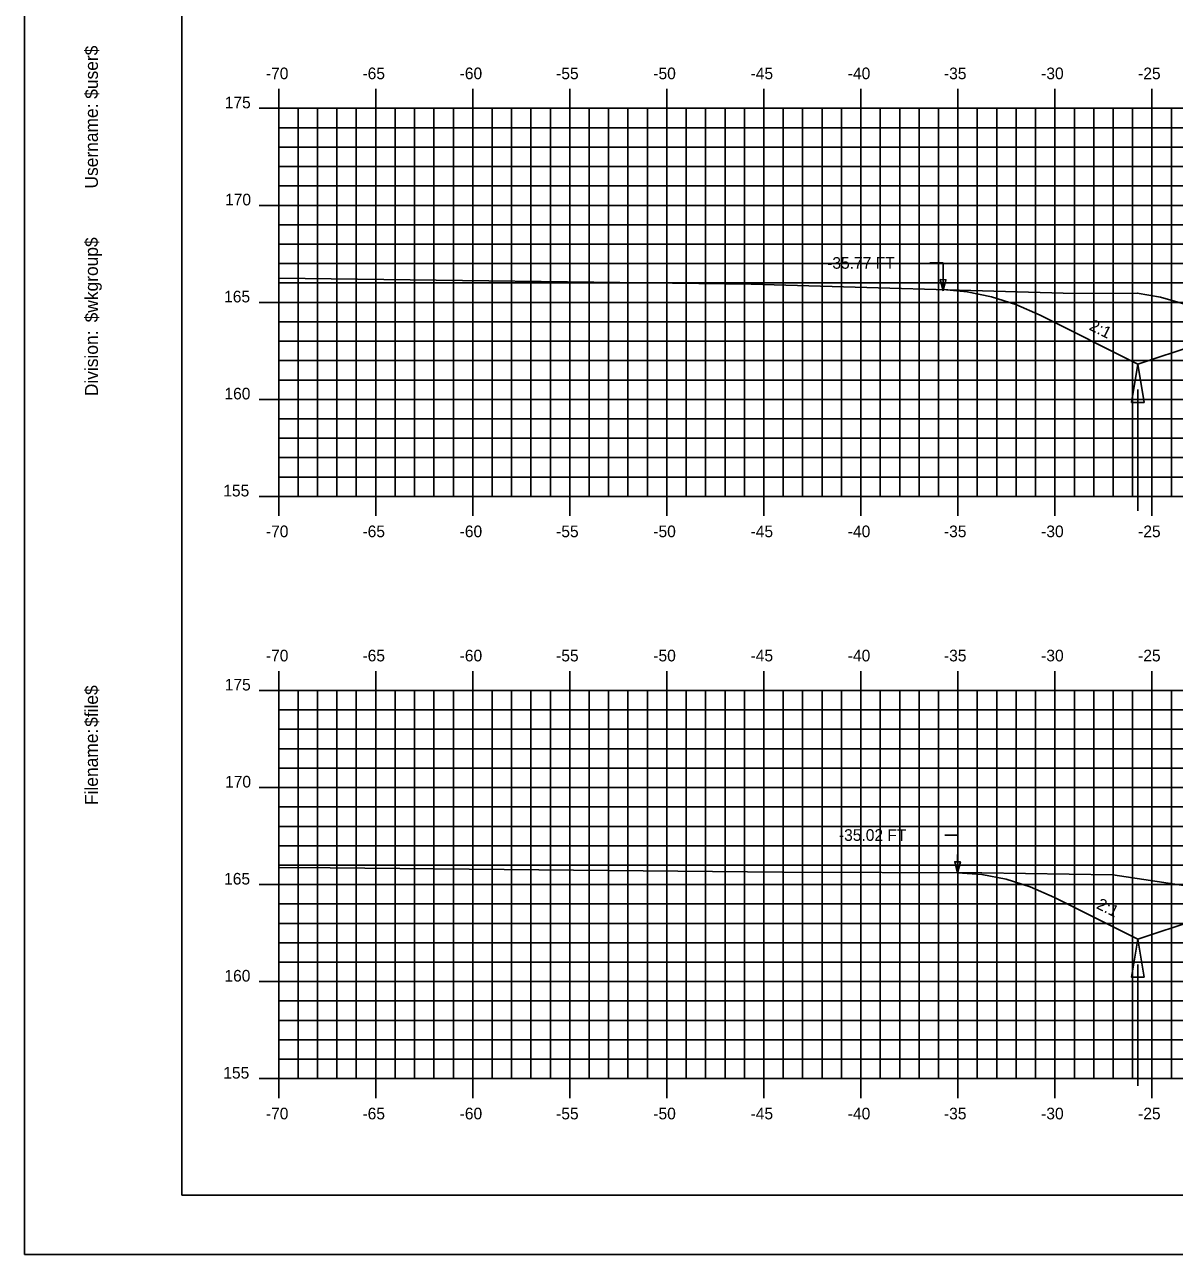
# Model space of a CAD drawing. Extents: x 1142533 to 1142703, y 608981 to 609091.
# Drawn here: x 1142533 to 1142592.2, y 608981.3 to 609044.6 of the extents above; entities that cross this region are included whole.
import ezdxf

# ---------------------------------------------------------------- set-up
doc = ezdxf.new("R2010")
doc.units = 0
for name, color, linetype in [('ANNOTATION', 7, 'Continuous'), ('BORDER', 7, 'Continuous'), ('D_Drainage_Ditch_Line', 7, 'Continuous'), ('D_Roadway_SlopeLines', 7, 'Continuous'), ('D_Text_Standard', 7, 'Continuous'), ('H_V ANNOTATION', 7, 'Continuous'), ('MAJOR', 7, 'Continuous'), ('MINOR', 7, 'Continuous'), ('PLOT BOUNDARY', 7, 'Continuous'), ('S_Roadway_Centerline', 7, 'Continuous')]:
    doc.layers.add(name, color=color, linetype=linetype)

msp = doc.modelspace()

# ---------------------------------------------------------------- linework, layer by layer
for points in [[(1142580.286, 609030.994), (1142581.536, 609030.885), (1142582.786, 609030.628), (1142584.036, 609030.224), (1142585.286, 609029.673), (1142590.329, 609027.152), (1142593.329, 609028.152), (1142601.052, 609030.726), (1142601.053, 609030.726), (1142605.053, 609030.886), (1142616.053, 609031.106), (1142627.053, 609030.886), (1142631.053, 609030.726), (1142638.777, 609028.152), (1142641.777, 609027.152), (1142645.788, 609029.157), (1142647.038, 609029.701), (1142648.288, 609030.083), (1142649.538, 609030.303), (1142650.788, 609030.361)], [(1142581.032, 609000.945), (1142582.282, 609000.857), (1142583.532, 609000.615), (1142584.782, 609000.22), (1142586.032, 608999.672), (1142590.329, 608997.523), (1142593.329, 608998.523), (1142601.052, 609001.098), (1142601.053, 609001.098), (1142605.053, 609001.258), (1142616.053, 609001.478), (1142627.053, 609001.258), (1142631.053, 609001.098), (1142638.777, 608998.523), (1142641.777, 608997.523), (1142646.306, 608999.787), (1142647.556, 609000.327), (1142648.806, 609000.696), (1142650.056, 609000.894), (1142651.306, 609000.921)]]:
    msp.add_lwpolyline(points)
at = {"layer": 'BORDER'}
msp.add_lwpolyline([(1142541.054, 608984.335), (1142701.054, 608984.335), (1142701.054, 609089.335), (1142541.054, 609089.335)], close=True, dxfattribs=at)
at = {"layer": 'D_Drainage_Ditch_Line'}
for p, q in [((1142590.329, 609025.839), (1142590.328, 609019.596)), ((1142590.329, 608996.211), (1142590.328, 608989.967))]:
    msp.add_line(p, q, dxfattribs=at)
for points in [[(1142590.657, 609025.183), (1142590.001, 609025.183), (1142590.329, 609027.152)], [(1142590.657, 608995.555), (1142590.001, 608995.555), (1142590.329, 608997.523)]]:
    msp.add_lwpolyline(points, close=True, dxfattribs=at)
at = {"layer": 'D_Roadway_SlopeLines'}
for points in [[(1142590.329, 609027.152), (1142585.286, 609029.673), (1142584.036, 609030.224), (1142582.786, 609030.628), (1142581.536, 609030.885), (1142580.286, 609030.994)], [(1142593.329, 609028.152), (1142590.329, 609027.152)], [(1142590.329, 608997.523), (1142586.032, 608999.672), (1142584.782, 609000.22), (1142583.532, 609000.615), (1142582.282, 609000.857), (1142581.032, 609000.945)], [(1142593.329, 608998.523), (1142590.329, 608997.523)]]:
    msp.add_lwpolyline(points, dxfattribs=at)
at = {"layer": 'D_Text_Standard'}
for points in [[(1142580.286, 609030.923), (1142580.291, 609032.368), (1142579.611, 609032.368)], [(1142581.032, 609000.922), (1142581.057, 609002.886), (1142580.377, 609002.886)]]:
    msp.add_lwpolyline(points, dxfattribs=at)
for points in [[(1142580.286, 609030.923), (1142580.142, 609031.506), (1142580.433, 609031.505)], [(1142581.032, 609000.922), (1142580.894, 609001.506), (1142581.185, 609001.502)]]:
    msp.add_lwpolyline(points, close=True, dxfattribs=at)
at = {"layer": 'MAJOR'}
for p, q in [((1142546.053, 609041.337), (1142546.053, 609040.335)), ((1142551.053, 609041.337), (1142551.053, 609040.335)), ((1142556.053, 609041.337), (1142556.053, 609040.335)), ((1142561.053, 609041.337), (1142561.053, 609040.335)), ((1142566.053, 609041.337), (1142566.053, 609040.335)), ((1142571.053, 609041.337), (1142571.053, 609040.335)), ((1142576.053, 609041.337), (1142576.053, 609040.335)), ((1142581.053, 609041.337), (1142581.053, 609040.335)), ((1142586.053, 609041.337), (1142586.053, 609040.335)), ((1142591.053, 609041.337), (1142591.053, 609040.335)), ((1142545.051, 609040.335), (1142546.053, 609040.335)), ((1142546.053, 609040.335), (1142686.053, 609040.335)), ((1142546.053, 609020.335), (1142546.053, 609040.335)), ((1142546.053, 609020.335), (1142546.053, 609040.335)), ((1142546.053, 609040.335), (1142686.053, 609040.335)), ((1142551.053, 609020.335), (1142551.053, 609040.335)), ((1142556.053, 609020.335), (1142556.053, 609040.335)), ((1142561.053, 609020.335), (1142561.053, 609040.335)), ((1142566.053, 609020.335), (1142566.053, 609040.335)), ((1142571.053, 609020.335), (1142571.053, 609040.335)), ((1142576.053, 609020.335), (1142576.053, 609040.335)), ((1142581.053, 609020.335), (1142581.053, 609040.335)), ((1142586.053, 609020.335), (1142586.053, 609040.335)), ((1142591.053, 609020.335), (1142591.053, 609040.335)), ((1142545.051, 609035.335), (1142546.053, 609035.335)), ((1142546.053, 609035.335), (1142686.053, 609035.335)), ((1142545.051, 609030.335), (1142546.053, 609030.335)), ((1142546.053, 609030.335), (1142686.053, 609030.335)), ((1142545.051, 609025.335), (1142546.053, 609025.335)), ((1142546.053, 609025.335), (1142686.053, 609025.335)), ((1142545.051, 609020.335), (1142546.053, 609020.335)), ((1142546.053, 609020.335), (1142686.053, 609020.335)), ((1142546.053, 609020.335), (1142686.053, 609020.335)), ((1142546.053, 609019.333), (1142546.053, 609020.335)), ((1142551.053, 609019.333), (1142551.053, 609020.335)), ((1142556.053, 609019.333), (1142556.053, 609020.335)), ((1142561.053, 609019.333), (1142561.053, 609020.335)), ((1142566.053, 609019.333), (1142566.053, 609020.335)), ((1142571.053, 609019.333), (1142571.053, 609020.335)), ((1142576.053, 609019.333), (1142576.053, 609020.335)), ((1142581.053, 609019.333), (1142581.053, 609020.335)), ((1142586.053, 609019.333), (1142586.053, 609020.335)), ((1142591.053, 609019.333), (1142591.053, 609020.335)), ((1142546.053, 609011.337), (1142546.053, 609010.335)), ((1142551.053, 609011.337), (1142551.053, 609010.335)), ((1142556.053, 609011.337), (1142556.053, 609010.335)), ((1142561.053, 609011.337), (1142561.053, 609010.335)), ((1142566.053, 609011.337), (1142566.053, 609010.335)), ((1142571.053, 609011.337), (1142571.053, 609010.335)), ((1142576.053, 609011.337), (1142576.053, 609010.335)), ((1142581.053, 609011.337), (1142581.053, 609010.335)), ((1142586.053, 609011.337), (1142586.053, 609010.335)), ((1142591.053, 609011.337), (1142591.053, 609010.335)), ((1142545.051, 609010.335), (1142546.053, 609010.335)), ((1142546.053, 609010.335), (1142686.053, 609010.335)), ((1142546.053, 608990.335), (1142546.053, 609010.335)), ((1142546.053, 608990.335), (1142546.053, 609010.335)), ((1142546.053, 609010.335), (1142686.053, 609010.335)), ((1142551.053, 608990.335), (1142551.053, 609010.335)), ((1142556.053, 608990.335), (1142556.053, 609010.335)), ((1142561.053, 608990.335), (1142561.053, 609010.335)), ((1142566.053, 608990.335), (1142566.053, 609010.335)), ((1142571.053, 608990.335), (1142571.053, 609010.335)), ((1142576.053, 608990.335), (1142576.053, 609010.335)), ((1142581.053, 608990.335), (1142581.053, 609010.335)), ((1142586.053, 608990.335), (1142586.053, 609010.335)), ((1142591.053, 608990.335), (1142591.053, 609010.335)), ((1142545.051, 609005.335), (1142546.053, 609005.335)), ((1142546.053, 609005.335), (1142686.053, 609005.335)), ((1142545.051, 609000.335), (1142546.053, 609000.335)), ((1142546.053, 609000.335), (1142686.053, 609000.335)), ((1142545.051, 608995.335), (1142546.053, 608995.335)), ((1142546.053, 608995.335), (1142686.053, 608995.335)), ((1142545.051, 608990.335), (1142546.053, 608990.335)), ((1142546.053, 608990.335), (1142686.053, 608990.335)), ((1142546.053, 608990.335), (1142686.053, 608990.335)), ((1142546.053, 608989.333), (1142546.053, 608990.335)), ((1142551.053, 608989.333), (1142551.053, 608990.335)), ((1142556.053, 608989.333), (1142556.053, 608990.335)), ((1142561.053, 608989.333), (1142561.053, 608990.335)), ((1142566.053, 608989.333), (1142566.053, 608990.335)), ((1142571.053, 608989.333), (1142571.053, 608990.335)), ((1142576.053, 608989.333), (1142576.053, 608990.335)), ((1142581.053, 608989.333), (1142581.053, 608990.335)), ((1142586.053, 608989.333), (1142586.053, 608990.335)), ((1142591.053, 608989.333), (1142591.053, 608990.335))]:
    msp.add_line(p, q, dxfattribs=at)
at = {"layer": 'MINOR'}
for p, q in [((1142547.053, 609020.335), (1142547.053, 609040.335)), ((1142548.053, 609020.335), (1142548.053, 609040.335)), ((1142549.053, 609020.335), (1142549.053, 609040.335)), ((1142550.053, 609020.335), (1142550.053, 609040.335)), ((1142552.053, 609020.335), (1142552.053, 609040.335)), ((1142553.053, 609020.335), (1142553.053, 609040.335)), ((1142554.053, 609020.335), (1142554.053, 609040.335)), ((1142555.053, 609020.335), (1142555.053, 609040.335)), ((1142557.053, 609020.335), (1142557.053, 609040.335)), ((1142558.053, 609020.335), (1142558.053, 609040.335)), ((1142559.053, 609020.335), (1142559.053, 609040.335)), ((1142560.053, 609020.335), (1142560.053, 609040.335)), ((1142562.053, 609020.335), (1142562.053, 609040.335)), ((1142563.053, 609020.335), (1142563.053, 609040.335)), ((1142564.053, 609020.335), (1142564.053, 609040.335)), ((1142565.053, 609020.335), (1142565.053, 609040.335)), ((1142567.053, 609020.335), (1142567.053, 609040.335)), ((1142568.053, 609020.335), (1142568.053, 609040.335)), ((1142569.053, 609020.335), (1142569.053, 609040.335)), ((1142570.053, 609020.335), (1142570.053, 609040.335)), ((1142572.053, 609020.335), (1142572.053, 609040.335)), ((1142573.053, 609020.335), (1142573.053, 609040.335)), ((1142574.053, 609020.335), (1142574.053, 609040.335)), ((1142575.053, 609020.335), (1142575.053, 609040.335)), ((1142577.053, 609020.335), (1142577.053, 609040.335)), ((1142578.053, 609020.335), (1142578.053, 609040.335)), ((1142579.053, 609020.335), (1142579.053, 609040.335)), ((1142580.053, 609020.335), (1142580.053, 609040.335)), ((1142582.053, 609020.335), (1142582.053, 609040.335)), ((1142583.053, 609020.335), (1142583.053, 609040.335)), ((1142584.053, 609020.335), (1142584.053, 609040.335)), ((1142585.053, 609020.335), (1142585.053, 609040.335)), ((1142587.053, 609020.335), (1142587.053, 609040.335)), ((1142588.053, 609020.335), (1142588.053, 609040.335)), ((1142589.053, 609020.335), (1142589.053, 609040.335)), ((1142590.053, 609020.335), (1142590.053, 609040.335)), ((1142592.053, 609020.335), (1142592.053, 609040.335)), ((1142546.053, 609039.335), (1142686.053, 609039.335)), ((1142546.053, 609039.335), (1142547.055, 609039.335)), ((1142546.053, 609038.335), (1142686.053, 609038.335)), ((1142546.053, 609038.335), (1142547.055, 609038.335)), ((1142546.053, 609037.335), (1142686.053, 609037.335)), ((1142546.053, 609037.335), (1142547.055, 609037.335)), ((1142546.053, 609036.335), (1142686.053, 609036.335)), ((1142546.053, 609036.335), (1142547.055, 609036.335)), ((1142546.053, 609034.335), (1142686.053, 609034.335)), ((1142546.053, 609034.335), (1142547.055, 609034.335)), ((1142546.053, 609033.335), (1142686.053, 609033.335)), ((1142546.053, 609033.335), (1142547.055, 609033.335)), ((1142546.053, 609032.335), (1142686.053, 609032.335)), ((1142546.053, 609032.335), (1142547.055, 609032.335)), ((1142546.053, 609031.335), (1142686.053, 609031.335)), ((1142546.053, 609031.335), (1142547.055, 609031.335)), ((1142546.053, 609029.335), (1142686.053, 609029.335)), ((1142546.053, 609029.335), (1142547.055, 609029.335)), ((1142546.053, 609028.335), (1142686.053, 609028.335)), ((1142546.053, 609028.335), (1142547.055, 609028.335)), ((1142546.053, 609027.335), (1142686.053, 609027.335)), ((1142546.053, 609027.335), (1142547.055, 609027.335)), ((1142546.053, 609026.335), (1142686.053, 609026.335)), ((1142546.053, 609026.335), (1142547.055, 609026.335)), ((1142546.053, 609024.335), (1142686.053, 609024.335)), ((1142546.053, 609024.335), (1142547.055, 609024.335)), ((1142546.053, 609023.335), (1142686.053, 609023.335)), ((1142546.053, 609023.335), (1142547.055, 609023.335)), ((1142546.053, 609022.335), (1142686.053, 609022.335)), ((1142546.053, 609022.335), (1142547.055, 609022.335)), ((1142546.053, 609021.335), (1142686.053, 609021.335)), ((1142546.053, 609021.335), (1142547.055, 609021.335)), ((1142547.053, 608990.335), (1142547.053, 609010.335)), ((1142548.053, 608990.335), (1142548.053, 609010.335)), ((1142549.053, 608990.335), (1142549.053, 609010.335)), ((1142550.053, 608990.335), (1142550.053, 609010.335)), ((1142552.053, 608990.335), (1142552.053, 609010.335)), ((1142553.053, 608990.335), (1142553.053, 609010.335)), ((1142554.053, 608990.335), (1142554.053, 609010.335)), ((1142555.053, 608990.335), (1142555.053, 609010.335)), ((1142557.053, 608990.335), (1142557.053, 609010.335)), ((1142558.053, 608990.335), (1142558.053, 609010.335)), ((1142559.053, 608990.335), (1142559.053, 609010.335)), ((1142560.053, 608990.335), (1142560.053, 609010.335)), ((1142562.053, 608990.335), (1142562.053, 609010.335)), ((1142563.053, 608990.335), (1142563.053, 609010.335)), ((1142564.053, 608990.335), (1142564.053, 609010.335)), ((1142565.053, 608990.335), (1142565.053, 609010.335)), ((1142567.053, 608990.335), (1142567.053, 609010.335)), ((1142568.053, 608990.335), (1142568.053, 609010.335)), ((1142569.053, 608990.335), (1142569.053, 609010.335)), ((1142570.053, 608990.335), (1142570.053, 609010.335)), ((1142572.053, 608990.335), (1142572.053, 609010.335)), ((1142573.053, 608990.335), (1142573.053, 609010.335)), ((1142574.053, 608990.335), (1142574.053, 609010.335)), ((1142575.053, 608990.335), (1142575.053, 609010.335)), ((1142577.053, 608990.335), (1142577.053, 609010.335)), ((1142578.053, 608990.335), (1142578.053, 609010.335)), ((1142579.053, 608990.335), (1142579.053, 609010.335)), ((1142580.053, 608990.335), (1142580.053, 609010.335)), ((1142582.053, 608990.335), (1142582.053, 609010.335)), ((1142583.053, 608990.335), (1142583.053, 609010.335)), ((1142584.053, 608990.335), (1142584.053, 609010.335)), ((1142585.053, 608990.335), (1142585.053, 609010.335)), ((1142587.053, 608990.335), (1142587.053, 609010.335)), ((1142588.053, 608990.335), (1142588.053, 609010.335)), ((1142589.053, 608990.335), (1142589.053, 609010.335)), ((1142590.053, 608990.335), (1142590.053, 609010.335)), ((1142592.053, 608990.335), (1142592.053, 609010.335)), ((1142546.053, 609009.335), (1142686.053, 609009.335)), ((1142546.053, 609009.335), (1142547.055, 609009.335)), ((1142546.053, 609008.335), (1142686.053, 609008.335)), ((1142546.053, 609008.335), (1142547.055, 609008.335)), ((1142546.053, 609007.335), (1142686.053, 609007.335)), ((1142546.053, 609007.335), (1142547.055, 609007.335)), ((1142546.053, 609006.335), (1142686.053, 609006.335)), ((1142546.053, 609006.335), (1142547.055, 609006.335)), ((1142546.053, 609004.335), (1142686.053, 609004.335)), ((1142546.053, 609004.335), (1142547.055, 609004.335)), ((1142546.053, 609003.335), (1142686.053, 609003.335)), ((1142546.053, 609003.335), (1142547.055, 609003.335)), ((1142546.053, 609002.335), (1142686.053, 609002.335)), ((1142546.053, 609002.335), (1142547.055, 609002.335)), ((1142546.053, 609001.335), (1142686.053, 609001.335)), ((1142546.053, 609001.335), (1142547.055, 609001.335)), ((1142546.053, 608999.335), (1142686.053, 608999.335)), ((1142546.053, 608999.335), (1142547.055, 608999.335)), ((1142546.053, 608998.335), (1142686.053, 608998.335)), ((1142546.053, 608998.335), (1142547.055, 608998.335)), ((1142546.053, 608997.335), (1142686.053, 608997.335)), ((1142546.053, 608997.335), (1142547.055, 608997.335)), ((1142546.053, 608996.335), (1142686.053, 608996.335)), ((1142546.053, 608996.335), (1142547.055, 608996.335)), ((1142546.053, 608994.335), (1142686.053, 608994.335)), ((1142546.053, 608994.335), (1142547.055, 608994.335)), ((1142546.053, 608993.335), (1142686.053, 608993.335)), ((1142546.053, 608993.335), (1142547.055, 608993.335)), ((1142546.053, 608992.335), (1142686.053, 608992.335)), ((1142546.053, 608992.335), (1142547.055, 608992.335)), ((1142546.053, 608991.335), (1142686.053, 608991.335)), ((1142546.053, 608991.335), (1142547.055, 608991.335))]:
    msp.add_line(p, q, dxfattribs=at)
at = {"layer": 'PLOT BOUNDARY'}
msp.add_lwpolyline([(1142532.96, 608981.276), (1142702.96, 608981.276), (1142702.96, 609091.276), (1142532.96, 609091.276)], close=True, dxfattribs=at)
at = {"layer": 'S_Roadway_Centerline'}
for points in [[(1142546.053, 609031.583), (1142570.408, 609031.275), (1142587.086, 609030.801), (1142590.294, 609030.814), (1142591.488, 609030.599), (1142594.777, 609029.667), (1142598.5, 609030.516), (1142599.061, 609030.651), (1142599.412, 609030.68), (1142602.144, 609030.775), (1142607.389, 609030.886), (1142613.313, 609031.057), (1142619.003, 609030.938), (1142624.666, 609030.747), (1142626.894, 609030.371), (1142628.418, 609030.242), (1142631.945, 609029.672), (1142633.786, 609029.252), (1142635.704, 609029.565), (1142638.328, 609030.59), (1142669.168, 609030.024), (1142672.845, 609029.979), (1142676.772, 609029.961), (1142686.053, 609029.887)], [(1142546.053, 609001.213), (1142548.7, 609001.192), (1142571.996, 609000.966), (1142582.291, 609000.942), (1142589.042, 609000.829), (1142592.574, 609000.311), (1142594.485, 609000.01), (1142595.627, 609000.223), (1142597.969, 609000.962), (1142599.526, 609001.079), (1142601.324, 609001.178), (1142605.502, 609001.265), (1142612.227, 609001.447), (1142618.838, 609001.201), (1142623.394, 609001.103), (1142625.788, 609000.67), (1142627.482, 609000.383), (1142629.79, 609000.093), (1142632.431, 608999.666), (1142639.118, 609000.611), (1142641.121, 609001.396), (1142656.974, 609000.657), (1142667.405, 609000.249), (1142686.053, 609000.083)]]:
    msp.add_lwpolyline(points, dxfattribs=at)

# ---------------------------------------------------------------- texts
at = {"layer": 'ANNOTATION'}
for p in [(1142587.774, 609028.947), (1142588.147, 608999.132)]:
    msp.add_text('2:1', height=0.6, rotation=333.43495, dxfattribs=at).set_placement(p)
at = {"layer": 'BORDER'}
for s, p in [('$user$', (1142536.739, 609040.827)), ('Username:', (1142536.739, 609036.203)), ('$wkgroup$', (1142536.739, 609029.305)), ('Division:', (1142536.739, 609025.501)), ('$file$', (1142536.739, 609008.461)), ('Filename:', (1142536.739, 609004.433))]:
    msp.add_text(s, height=0.6696, rotation=90, dxfattribs=at).set_placement(p)
at = {"layer": 'D_Text_Standard'}
for s, p in [('-35.77 FT', (1142574.316, 609032.068)), ('-35.02 FT', (1142574.922, 609002.586))]:
    msp.add_text(s, height=0.6, dxfattribs=at).set_placement(p)
at = {"layer": 'H_V ANNOTATION'}
for s, p in [('-70', (1142545.395, 609041.835)), ('-65', (1142550.371, 609041.835)), ('-60', (1142555.379, 609041.835)), ('-55', (1142560.35, 609041.835)), ('-50', (1142565.358, 609041.835)), ('-45', (1142570.371, 609041.835)), ('-40', (1142575.379, 609041.835)), ('-35', (1142580.334, 609041.835)), ('-30', (1142585.342, 609041.835)), ('-25', (1142590.339, 609041.835)), ('175', (1142543.274, 609040.335)), ('170', (1142543.29, 609035.335)), ('165', (1142543.242, 609030.335)), ('160', (1142543.258, 609025.335)), ('155', (1142543.199, 609020.335)), ('-70', (1142545.395, 609018.235)), ('-65', (1142550.371, 609018.235)), ('-60', (1142555.379, 609018.235)), ('-55', (1142560.35, 609018.235)), ('-50', (1142565.358, 609018.235)), ('-45', (1142570.371, 609018.235)), ('-40', (1142575.379, 609018.235)), ('-35', (1142580.334, 609018.235)), ('-30', (1142585.342, 609018.235)), ('-25', (1142590.339, 609018.235)), ('-70', (1142545.395, 609011.835)), ('-65', (1142550.371, 609011.835)), ('-60', (1142555.379, 609011.835)), ('-55', (1142560.35, 609011.835)), ('-50', (1142565.358, 609011.835)), ('-45', (1142570.371, 609011.835)), ('-40', (1142575.379, 609011.835)), ('-35', (1142580.334, 609011.835)), ('-30', (1142585.342, 609011.835)), ('-25', (1142590.339, 609011.835)), ('175', (1142543.274, 609010.335)), ('170', (1142543.29, 609005.335)), ('165', (1142543.242, 609000.335)), ('160', (1142543.258, 608995.335)), ('155', (1142543.199, 608990.335)), ('-70', (1142545.395, 608988.235)), ('-65', (1142550.371, 608988.235)), ('-60', (1142555.379, 608988.235)), ('-55', (1142560.35, 608988.235)), ('-50', (1142565.358, 608988.235)), ('-45', (1142570.371, 608988.235)), ('-40', (1142575.379, 608988.235)), ('-35', (1142580.334, 608988.235)), ('-30', (1142585.342, 608988.235)), ('-25', (1142590.339, 608988.235))]:
    msp.add_text(s, height=0.6, dxfattribs=at).set_placement(p)
at = {"layer": 'MAJOR'}
for p in [(1142546.049, 609020.335), (1142546.049, 608990.335)]:
    msp.add_text('-', height=0.006, dxfattribs=at).set_placement(p)

doc.saveas('drawing.dxf')
